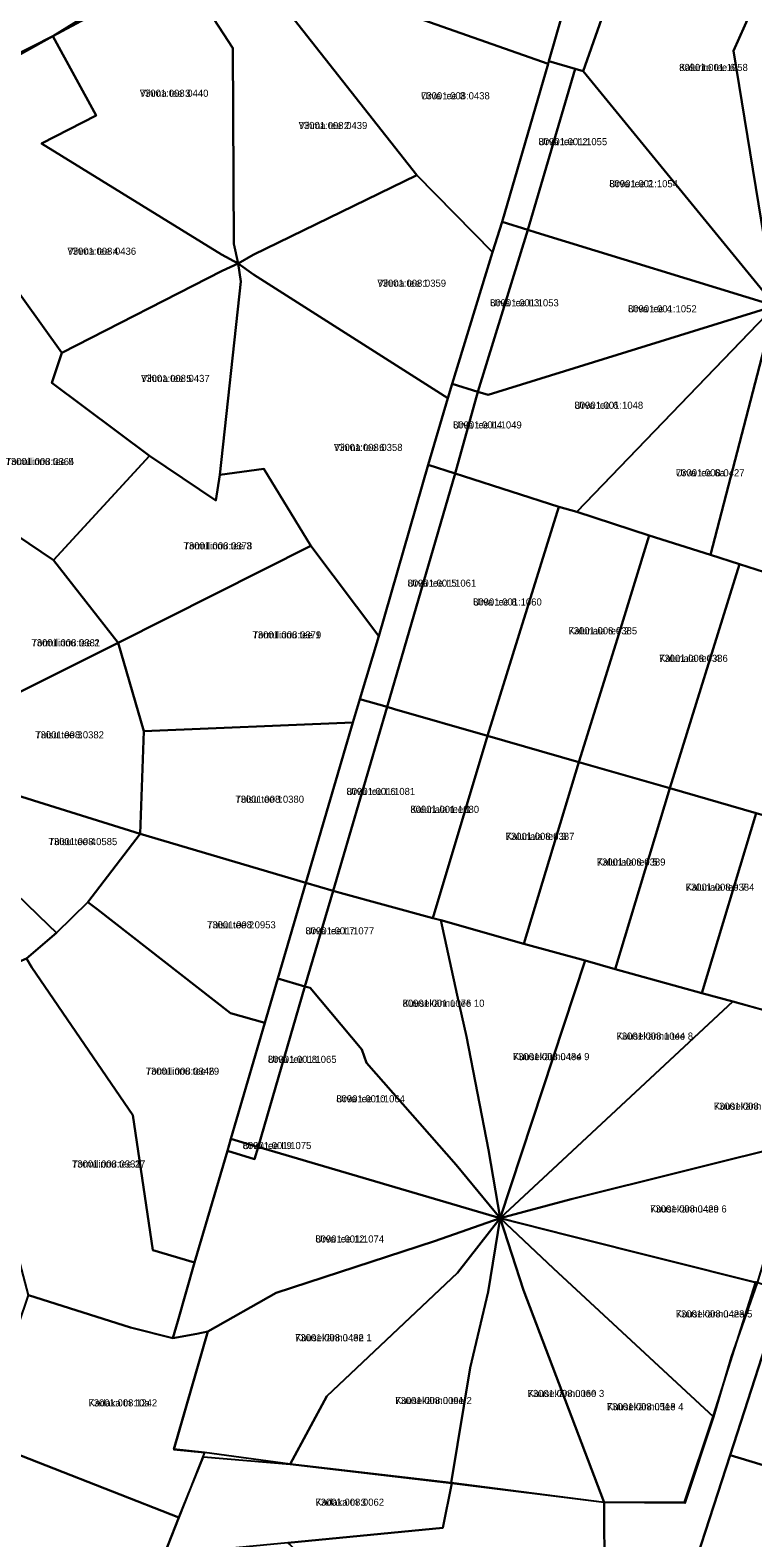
# Model space of a CAD drawing. Extents: x 524000 to 564260, y 6469338 to 6496391.
# Drawn here: x 534770.1 to 534922.8, y 6471075.8 to 6471394 of the extents above; entities that cross this region are included whole.
import ezdxf

# ---------------------------------------------------------------- set-up
doc = ezdxf.new("R2010")
doc.units = 0
for name, color, linetype in [('L_AADRESS', 7, 'Continuous'), ('PIIR', 7, 'Continuous'), ('TUNNUS', 7, 'Continuous')]:
    doc.layers.add(name, color=color, linetype=linetype)

msp = doc.modelspace()

# ---------------------------------------------------------------- linework, layer by layer
at = {"layer": 'PIIR'}
for points in [[(534780.82, 6471396.34), (534774.97, 6471392.67), (534761.55, 6471385.92), (534759.86, 6471389.49), (534732.39, 6471447.56), (534750.64, 6471457.14), (534779.27, 6471399.47)], [(534891.27, 6471427.11), (534889.35, 6471420.96), (534879.65, 6471387.43), (534879.52, 6471386.83), (534837.43, 6471401.7), (534825.87, 6471396.18), (534815.22, 6471408.66), (534811.83, 6471412.65), (534820.45, 6471416.26), (534823.72, 6471417.88), (534826.89, 6471419.63), (534845.17, 6471429.76), (534851.35, 6471433.33), (534853.52, 6471429.3), (534854.83, 6471426.87), (534891.13, 6471445.07), (534885.67, 6471428.8)], [(534879.65, 6471387.43), (534889.35, 6471420.96), (534897.68, 6471415.89), (534886.94, 6471385.29), (534885.21, 6471385.79)], [(534886.94, 6471385.29), (534897.68, 6471415.89), (534923.42, 6471400.31), (534918.64, 6471389.57), (534927.44, 6471335.81)], [(534814.05, 6471344.7), (534813.18, 6471348.88), (534812.97, 6471390.13), (534801.9, 6471407.19), (534811.83, 6471412.65), (534825.87, 6471396.18), (534851.78, 6471363.34), (534817.24, 6471346.57)], [(534784.08, 6471375.92), (534774.97, 6471392.67), (534801.9, 6471407.19), (534812.97, 6471390.13), (534813.18, 6471348.88), (534814.05, 6471344.7), (534810.56, 6471346.59), (534772.52, 6471370.01)], [(534825.87, 6471396.18), (534837.43, 6471401.7), (534879.52, 6471386.83), (534869.8, 6471353.48), (534867.81, 6471347.11), (534851.78, 6471363.34)], [(534918.64, 6471389.57), (534923.42, 6471400.31), (534933.99, 6471395.58), (534949.13, 6471397.18), (534927.44, 6471335.81)], [(534742, 6471374.42), (534774.97, 6471392.67), (534784.08, 6471375.92), (534772.52, 6471370.01), (534810.56, 6471346.59), (534814.05, 6471344.7), (534810.68, 6471343.15), (534776.82, 6471325.86), (534744.08, 6471371.45)], [(534879.52, 6471386.83), (534879.65, 6471387.43), (534885.21, 6471385.79), (534875.27, 6471351.81), (534869.8, 6471353.48)], [(534875.27, 6471351.81), (534885.21, 6471385.79), (534886.94, 6471385.29), (534927.44, 6471335.81), (534877, 6471351.28)], [(534734.59, 6471370.43), (534742, 6471374.42), (534744.08, 6471371.45), (534776.82, 6471325.86), (534774.75, 6471319.56), (534795.34, 6471304.11), (534775.06, 6471282.13), (534767.27, 6471287.36), (534757.36, 6471290.47), (534766.71, 6471322.18), (534737.05, 6471366.7)], [(534814.05, 6471344.7), (534817.24, 6471346.57), (534851.78, 6471363.34), (534867.81, 6471347.11), (534859.27, 6471319.28), (534858.38, 6471316.27), (534817.28, 6471342.41)], [(534867.81, 6471347.11), (534869.8, 6471353.48), (534875.27, 6471351.81), (534864.69, 6471317.65), (534859.27, 6471319.28)], [(534864.69, 6471317.65), (534875.27, 6471351.81), (534877, 6471351.28), (534927.44, 6471335.81), (534866.89, 6471316.99)], [(534774.75, 6471319.56), (534776.82, 6471325.86), (534810.68, 6471343.15), (534814.05, 6471344.7), (534814.66, 6471340.9), (534810.17, 6471300.12), (534809.38, 6471294.72), (534795.34, 6471304.11)], [(534819.47, 6471301.36), (534810.17, 6471300.12), (534814.66, 6471340.9), (534814.05, 6471344.7), (534817.28, 6471342.41), (534858.38, 6471316.27), (534854.2, 6471302.24), (534843.75, 6471266.08), (534829.43, 6471285.14)], [(534859.9, 6471300.4), (534864.69, 6471317.65), (534866.89, 6471316.99), (534927.44, 6471335.81), (534885.56, 6471292.27), (534881.82, 6471293.39), (534861.63, 6471299.84)], [(534885.56, 6471292.27), (534927.44, 6471335.81), (534913.83, 6471283.22), (534900.88, 6471287.32)], [(534942.2, 6471276.03), (534941.06, 6471274.53), (534919.94, 6471281.26), (534913.83, 6471283.22), (534927.44, 6471335.81)], [(534858.38, 6471316.27), (534859.27, 6471319.28), (534864.69, 6471317.65), (534859.9, 6471300.4), (534854.2, 6471302.24)], [(534775.06, 6471282.13), (534795.34, 6471304.11), (534809.38, 6471294.72), (534810.17, 6471300.12), (534819.47, 6471301.36), (534829.43, 6471285.14), (534788.75, 6471264.66)], [(534843.75, 6471266.08), (534854.2, 6471302.24), (534859.9, 6471300.4), (534845.54, 6471251.12), (534839.77, 6471252.76)], [(534845.54, 6471251.12), (534859.9, 6471300.4), (534861.63, 6471299.84), (534881.82, 6471293.39), (534866.75, 6471245), (534847.05, 6471250.67)], [(534866.75, 6471245), (534881.82, 6471293.39), (534885.56, 6471292.27), (534900.88, 6471287.32), (534894.55, 6471266.67), (534885.98, 6471239.48)], [(534743.64, 6471246.88), (534767.27, 6471287.36), (534775.06, 6471282.13), (534788.75, 6471264.66), (534740.34, 6471240.49)], [(534788.75, 6471264.66), (534829.43, 6471285.14), (534843.75, 6471266.08), (534839.77, 6471252.76), (534838.32, 6471247.82), (534794.17, 6471246.04)], [(534894.55, 6471266.67), (534900.88, 6471287.32), (534913.83, 6471283.22), (534919.94, 6471281.26), (534905.2, 6471233.96), (534885.98, 6471239.48)], [(534941.06, 6471274.53), (534939.48, 6471272.15), (534937.72, 6471258.32), (534935.29, 6471239.21), (534935.04, 6471237.33), (534931.84, 6471226.29), (534923.45, 6471228.7), (534905.2, 6471233.96), (534919.94, 6471281.26)], [(534788.75, 6471264.66), (534794.17, 6471246.04), (534793.38, 6471224.32), (534748.04, 6471238.49), (534740.34, 6471240.49)], [(534838.32, 6471247.82), (534839.77, 6471252.76), (534845.54, 6471251.12), (534834.13, 6471212.32), (534828.36, 6471213.97)], [(534834.13, 6471212.32), (534845.54, 6471251.12), (534847.05, 6471250.67), (534866.75, 6471245), (534855.15, 6471206.52), (534835.63, 6471211.89)], [(534794.17, 6471246.04), (534838.32, 6471247.82), (534828.36, 6471213.97), (534793.38, 6471224.32)], [(534866.75, 6471245), (534885.98, 6471239.48), (534874.4, 6471201.14), (534856.84, 6471206.09), (534855.15, 6471206.52)], [(534740.34, 6471240.49), (534744.22, 6471233.85), (534774.01, 6471205.05), (534775.68, 6471203.44), (534769.39, 6471198.01), (534753.09, 6471191.01), (534734.76, 6471189.19), (534725.97, 6471190.68), (534726.66, 6471192.99), (534738.63, 6471233)], [(534740.34, 6471240.49), (534748.04, 6471238.49), (534793.38, 6471224.32), (534782.33, 6471209.95), (534775.68, 6471203.44), (534774.01, 6471205.05), (534744.22, 6471233.85)], [(534885.98, 6471239.48), (534905.2, 6471233.96), (534893.68, 6471195.81), (534887.32, 6471197.6), (534874.4, 6471201.14)], [(534923.45, 6471228.7), (534931.84, 6471226.29), (534935.04, 6471237.33), (534944.19, 6471219.61), (534931.84, 6471185.26), (534918.53, 6471188.99), (534911.99, 6471190.75)], [(534905.2, 6471233.96), (534923.45, 6471228.7), (534911.99, 6471190.75), (534893.68, 6471195.81)], [(534782.33, 6471209.95), (534793.38, 6471224.32), (534828.36, 6471213.97), (534822.44, 6471193.81), (534819.71, 6471184.46), (534812.45, 6471186.51), (534784.3, 6471208.42)], [(534822.44, 6471193.81), (534828.36, 6471213.97), (534834.13, 6471212.32), (534828.17, 6471192.13)], [(534828.17, 6471192.13), (534834.13, 6471212.32), (534835.63, 6471211.89), (534855.15, 6471206.52), (534856.84, 6471206.09), (534860.32, 6471190.3), (534862.31, 6471181.55), (534866.96, 6471157.63), (534869.4, 6471143.24), (534860.13, 6471154.5), (534841.19, 6471176.04), (534840.2, 6471178.83), (534829.25, 6471191.83)], [(534791.83, 6471164.95), (534770.49, 6471196.15), (534769.39, 6471198.01), (534775.68, 6471203.44), (534782.33, 6471209.95), (534784.3, 6471208.42), (534812.45, 6471186.51), (534819.71, 6471184.46), (534812.53, 6471159.96), (534811.79, 6471157.46), (534804.86, 6471133.88), (534796.04, 6471136.47)], [(534866.96, 6471157.63), (534862.31, 6471181.55), (534860.32, 6471190.3), (534856.84, 6471206.09), (534874.4, 6471201.14), (534887.32, 6471197.6), (534869.4, 6471143.24)], [(534753.09, 6471191.01), (534769.39, 6471198.01), (534770.49, 6471196.15), (534791.83, 6471164.95), (534796.04, 6471136.47), (534804.86, 6471133.88), (534801.31, 6471121.49), (534800.29, 6471117.93), (534791.37, 6471120.19), (534769.81, 6471126.97), (534753.6, 6471188.2)], [(534880.5, 6471153.54), (534869.4, 6471143.24), (534887.32, 6471197.6), (534893.68, 6471195.81), (534911.99, 6471190.75), (534918.53, 6471188.99)], [(534819.71, 6471184.46), (534822.44, 6471193.81), (534828.17, 6471192.13), (534818.28, 6471158.25), (534812.53, 6471159.96)], [(534818.28, 6471158.25), (534828.17, 6471192.13), (534829.25, 6471191.83), (534840.2, 6471178.83), (534841.19, 6471176.04), (534860.13, 6471154.5), (534869.4, 6471143.24), (534819.45, 6471157.91)], [(534869.4, 6471143.24), (534880.5, 6471153.54), (534918.53, 6471188.99), (534931.8, 6471185.27), (534938.53, 6471176.53), (534932.7, 6471159.28), (534884.38, 6471147.21)], [(534804.86, 6471133.88), (534811.79, 6471157.46), (534817.51, 6471155.66), (534818.28, 6471158.25), (534819.45, 6471157.91), (534869.4, 6471143.24), (534855.56, 6471138.38), (534822.1, 6471127.49), (534807.69, 6471119.28), (534805.33, 6471118.85), (534800.29, 6471117.93), (534801.31, 6471121.49)], [(534811.79, 6471157.46), (534812.53, 6471159.96), (534818.28, 6471158.25), (534817.51, 6471155.66)], [(534869.4, 6471143.24), (534884.38, 6471147.21), (534932.7, 6471159.28), (534923.7, 6471129.58), (534883.86, 6471139.54)], [(534917.95, 6471093.22), (534929.17, 6471127.81), (534937.27, 6471152.88), (534961.44, 6471145.95), (534953.8, 6471121.19), (534942.82, 6471085.67)], [(534869.4, 6471143.24), (534860.4, 6471131.71), (534832.8, 6471105.64), (534825.08, 6471091.28), (534806.96, 6471093.79), (534800.51, 6471094.46), (534807.69, 6471119.28), (534822.1, 6471127.49), (534855.56, 6471138.38)], [(534832.8, 6471105.64), (534860.4, 6471131.71), (534869.4, 6471143.24), (534866.88, 6471127.71), (534863.03, 6471111.64), (534859.05, 6471087.37), (534825.08, 6471091.28)], [(534874.3, 6471128.04), (534891.34, 6471083.21), (534859.05, 6471087.37), (534863.03, 6471111.64), (534866.88, 6471127.71), (534869.4, 6471143.24)], [(534869.4, 6471143.24), (534883.86, 6471139.54), (534923.7, 6471129.58), (534918.17, 6471113.97), (534914.45, 6471101.32), (534880.69, 6471132.6)], [(534874.3, 6471128.04), (534869.4, 6471143.24), (534880.69, 6471132.6), (534914.45, 6471101.32), (534908.36, 6471083.09), (534891.34, 6471083.21)], [(534829.59, 6470945.37), (534814.26, 6470952.72), (534840.6, 6471002.76), (534852.28, 6471024.93), (534861.12, 6471041.72), (534891.41, 6471067.57), (534891.38, 6471083.26), (534908.34, 6471083.29), (534914.41, 6471101.56), (534923.35, 6471129.83), (534929.17, 6471127.81), (534917.95, 6471093.22), (534906.63, 6471058.29), (534892, 6471045.77), (534874.65, 6471030.92), (534868.45, 6471019.07), (534865.19, 6471012.88), (534854.25, 6470992.18)], [(534769.81, 6471126.97), (534791.37, 6471120.19), (534800.29, 6471117.93), (534805.33, 6471118.85), (534807.69, 6471119.28), (534800.5, 6471094.44), (534806.96, 6471093.79), (534801.51, 6471080.03), (534759.42, 6471096.54)], [(534759.42, 6471096.54), (534801.51, 6471080.03), (534798.46, 6471072.18), (534789.9, 6471050.41), (534749.27, 6471066.34)], [(534806.72, 6471092.89), (534825.08, 6471091.28), (534859.2, 6471087.33), (534857.32, 6471077.91), (534824.55, 6471074.72), (534801.81, 6471072.51), (534798.46, 6471072.18), (534801.51, 6471080.03)], [(534892, 6471045.77), (534906.63, 6471058.29), (534917.95, 6471093.22), (534942.82, 6471085.67), (534933.19, 6471054.88), (534929.62, 6471043.08), (534925.04, 6471028.2)], [(534891.38, 6471083.26), (534891.41, 6471067.57), (534861.12, 6471041.72), (534824.55, 6471074.72), (534857.32, 6471077.91), (534859.2, 6471087.33)]]:
    msp.add_lwpolyline(points, close=True, dxfattribs=at)

# ---------------------------------------------------------------- texts
at = {"layer": 'L_AADRESS'}
for s, p in [('Kalurite tee 6', (534907.19, 6471385.34)), ('Vihma tee 3', (534793.29, 6471379.89)), ('Urva tee 3', (534852.7, 6471379.36)), ('Vihma tee 2', (534826.84, 6471373.09)), ('Urva tee L2', (534877.5, 6471369.68)), ('Urva tee 2', (534892.44, 6471360.8)), ('Vihma tee 4', (534778.02, 6471346.55)), ('Vihma tee 1', (534843.47, 6471339.8)), ('Urva tee L3', (534867.27, 6471335.67)), ('Urva tee 4', (534896.39, 6471334.4)), ('Vihma tee 5', (534793.56, 6471319.71)), ('Urva tee 6', (534885.09, 6471314.04)), ('Urva tee L4', (534859.45, 6471309.89)), ('Vihma tee 6', (534834.28, 6471305.15)), ('Tormilinnu tee 5', (534764.97, 6471302.17)), ('Urva tee 6a', (534906.5, 6471299.79)), ('Tormilinnu tee 3', (534802.54, 6471284.38)), ('Urva tee L5', (534849.84, 6471276.5)), ('Urva tee 8', (534863.68, 6471272.53)), ('Tormilinnu tee 2', (534770.43, 6471263.92)), ('Tormilinnu tee 1', (534817.1, 6471265.59)), ('Kaluriaia tee 2', (534883.82, 6471266.45)), ('Kaluriaia tee 4', (534902.96, 6471260.63)), ('Tuisu tee 3', (534771.23, 6471244.49)), ('Urva tee L6', (534836.95, 6471232.54)), ('Tuisu tee 1', (534813.48, 6471230.9)), ('Kaluriaia tee 1', (534850.44, 6471228.76)), ('Kaluriaia tee 3', (534870.56, 6471223.06)), ('Tuisu tee 4', (534774.04, 6471221.96)), ('Kaluriaia tee 5', (534889.8, 6471217.64)), ('Kaluriaia tee 7', (534908.57, 6471212.34)), ('Tuisu tee 2', (534807.51, 6471204.39)), ('Urva tee L7', (534828.29, 6471203.12)), ('Kuusekännu tee 10', (534848.79, 6471187.84)), ('Kuusekännu tee 8', (534893.96, 6471180.91)), ('Urva tee L8', (534820.35, 6471176)), ('Kuusekännu tee 9', (534872.08, 6471176.58)), ('Tormilinnu tee 29', (534794.55, 6471173.5)), ('Urva tee 10', (534834.79, 6471167.68)), ('Kuusekännu tee 7', (534914.5, 6471166.11)), ('Urva tee L9', (534815.02, 6471157.81)), ('Tormilinnu tee 27', (534778.98, 6471153.92)), ('Kuusekännu tee 6', (534901.05, 6471144.43)), ('Urva tee 12', (534830.38, 6471138.09)), ('Kuusekännu tee 5', (534906.47, 6471122.28)), ('Kuusekännu tee 1', (534826.1, 6471117.26)), ('Kuusekännu tee 3', (534875.2, 6471105.49)), ('Kadaka tn 10a', (534782.46, 6471103.5)), ('Kuusekännu tee 2', (534847.24, 6471104)), ('Kuusekännu tee 4', (534891.93, 6471102.7)), ('Kadaka tn 3', (534830.38, 6471082.54))]:
    msp.add_text(s, height=1.5, dxfattribs=at).set_placement(p)
at = {"layer": 'TUNNUS'}
for s, p in [('80901:001:1058', (534907.19, 6471385.34)), ('73001:008:0440', (534793.29, 6471379.89)), ('73001:008:0438', (534852.7, 6471379.36)), ('73001:008:0439', (534826.84, 6471373.09)), ('80901:001:1055', (534877.5, 6471369.68)), ('80901:001:1054', (534892.44, 6471360.8)), ('73001:008:0436', (534778.02, 6471346.55)), ('73001:008:0359', (534843.47, 6471339.8)), ('80901:001:1053', (534867.27, 6471335.67)), ('80901:001:1052', (534896.39, 6471334.4)), ('73001:008:0437', (534793.56, 6471319.71)), ('80901:001:1048', (534885.09, 6471314.04)), ('80901:001:1049', (534859.45, 6471309.89)), ('73001:008:0358', (534834.28, 6471305.15)), ('73001:008:0364', (534764.97, 6471302.17)), ('73001:008:0427', (534906.5, 6471299.79)), ('73001:008:0378', (534802.54, 6471284.38)), ('80901:001:1061', (534849.84, 6471276.5)), ('80901:001:1060', (534863.68, 6471272.53)), ('73001:008:0381', (534770.43, 6471263.92)), ('73001:008:0379', (534817.1, 6471265.59)), ('73001:008:0385', (534883.82, 6471266.45)), ('73001:008:0386', (534902.96, 6471260.63)), ('73001:008:0382', (534771.23, 6471244.49)), ('80901:001:1081', (534836.95, 6471232.54)), ('73001:008:0380', (534813.48, 6471230.9)), ('80901:001:1080', (534850.44, 6471228.76)), ('73001:008:0387', (534870.56, 6471223.06)), ('73001:008:0585', (534774.04, 6471221.96)), ('73001:008:0389', (534889.8, 6471217.64)), ('73001:008:0384', (534908.57, 6471212.34)), ('73001:008:0953', (534807.51, 6471204.39)), ('80901:001:1077', (534828.29, 6471203.12)), ('80901:001:1076', (534848.79, 6471187.84)), ('73001:008:1044', (534893.96, 6471180.91)), ('80901:001:1065', (534820.35, 6471176)), ('73001:008:0434', (534872.08, 6471176.58)), ('73001:008:0346', (534794.55, 6471173.5)), ('80901:001:1064', (534834.79, 6471167.68)), ('73001:008:1549', (534914.5, 6471166.11)), ('80901:001:1075', (534815.02, 6471157.81)), ('73001:008:0331', (534778.98, 6471153.92)), ('73001:008:0429', (534901.05, 6471144.43)), ('80901:001:1074', (534830.38, 6471138.09)), ('73001:008:0423', (534906.47, 6471122.28)), ('73001:008:0432', (534826.1, 6471117.26)), ('73001:008:0060', (534875.2, 6471105.49)), ('73001:008:1242', (534782.46, 6471103.5)), ('73001:008:0091', (534847.24, 6471104)), ('73001:008:0518', (534891.93, 6471102.7)), ('73001:008:0062', (534830.38, 6471082.54))]:
    msp.add_text(s, height=1.5, dxfattribs=at).set_placement(p)

doc.saveas('drawing.dxf')
